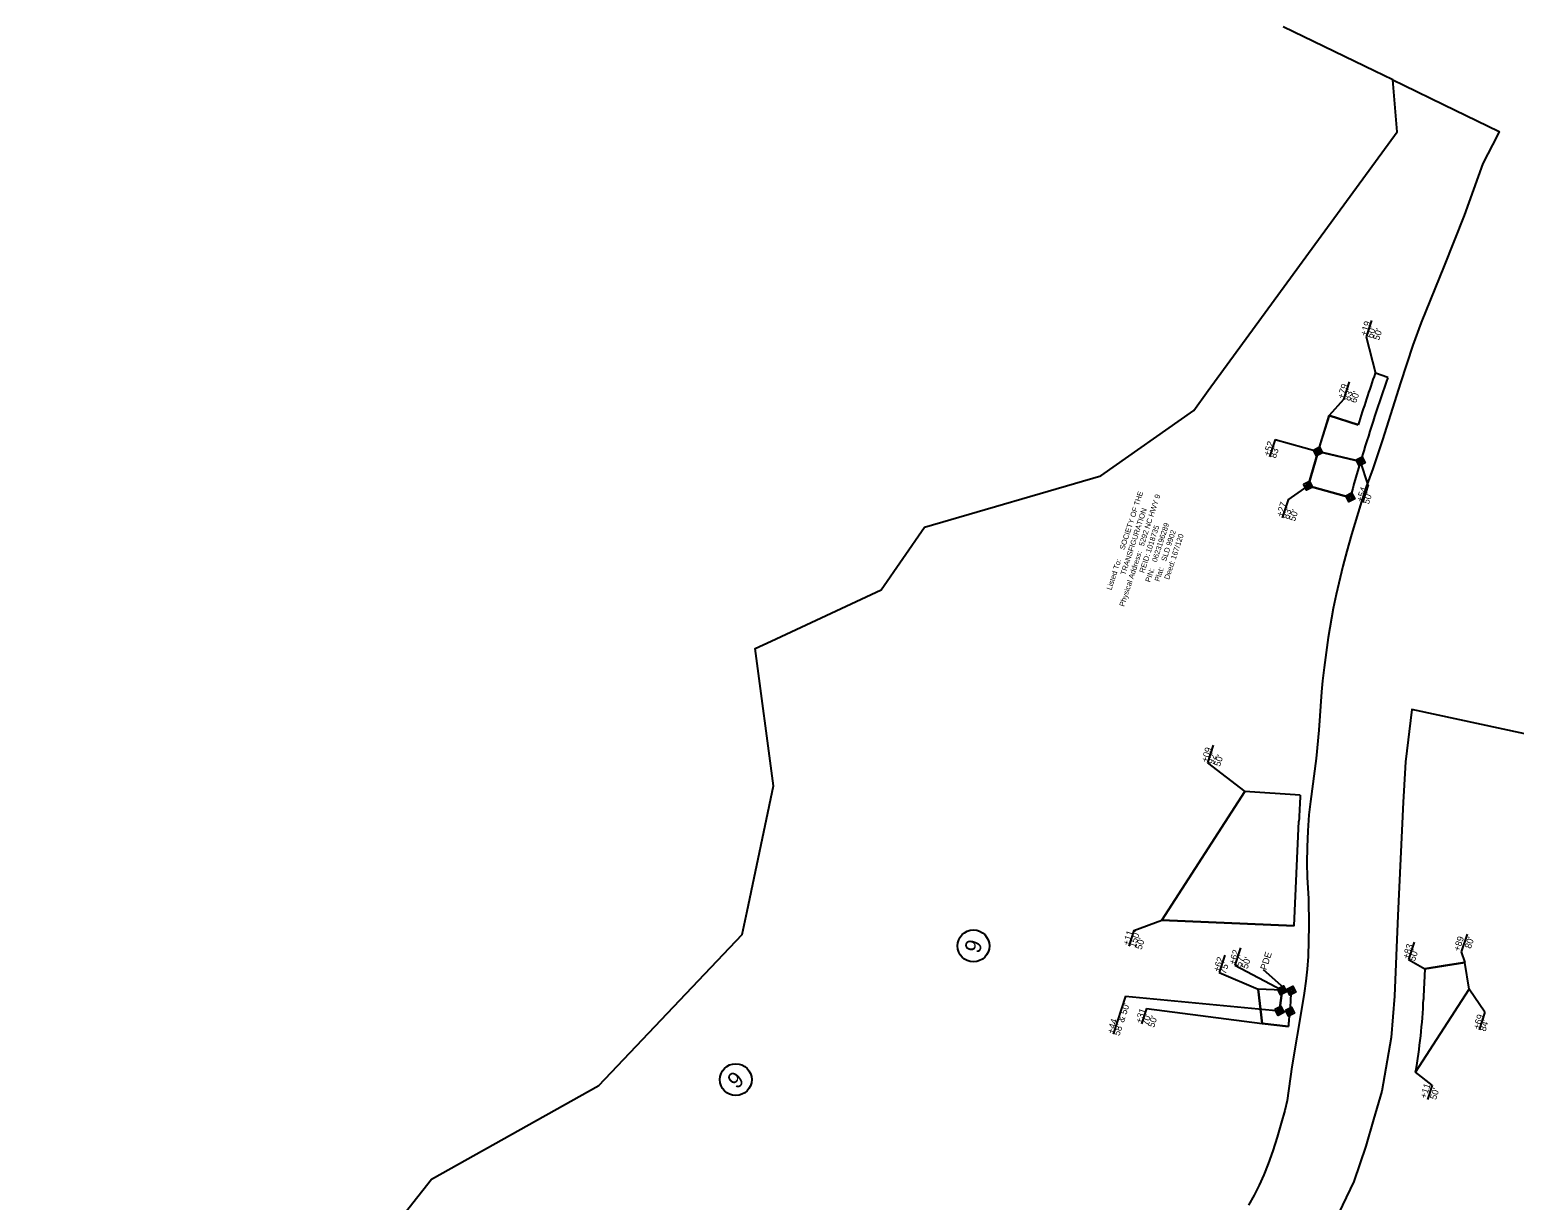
# Model space of a CAD drawing. Extents: x 1019969 to 1024963, y 638146 to 643978.
# Drawn here: x 1021048 to 1022170, y 639172 to 640057 of the extents above; entities that cross this region are included whole.
import ezdxf

# ---------------------------------------------------------------- set-up
doc = ezdxf.new("R2010")
doc.units = 0
for name, color, linetype in [('Old_Level_30', 7, 'Continuous'), ('Pattern 2', 7, 'Continuous'), ('Pattern 5', 7, 'Continuous'), ('Pattern 6', 7, 'Continuous'), ('Prop Easement Construction', 7, 'Continuous'), ('Prop Easement Construction Station Offsets', 7, 'Continuous'), ('Prop Easement Permanent Drainage', 7, 'Continuous'), ('Prop Easement Permanent Drainage Station Offsets', 7, 'Continuous'), ('Prop Parcel Number CELL', 7, 'Continuous'), ('Prop Parcel Owner Text', 7, 'Continuous'), ('Prop ROW Marker CELL', 7, 'Continuous'), ('Prop ROW Permanent Easement CELL', 7, 'Continuous'), ('Prop ROW RW Lines', 7, 'Continuous')]:
    doc.layers.add(name, color=color, linetype=linetype)

msp = doc.modelspace()

# ---------------------------------------------------------------- linework, layer by layer
at = {"layer": 'Old_Level_30'}
for points in [[(1021148.4, 638700.1), (1021154.9, 638708.9), (1021160.9, 638716.8), (1021048.3, 638820.3), (1021060.8, 638834.8), (1021201.8, 638998.1), (1021351.8, 639188.4), (1021478.2, 639259.2), (1021586.5, 639373.1), (1021590.2, 639390.9), (1021610.1, 639485.6), (1021596.2, 639589.1), (1021608.3, 639594.8), (1021691.4, 639633.5), (1021724, 639680.8), (1021857.3, 639719.7), (1021927.5, 639769), (1021938.4, 639784), (1022081, 639979.4), (1022077.7, 640018.6), (1022070.6, 640022.1), (1022064.2, 640025.1), (1021995.1, 640058.6)], [(1021201.8, 638998.1), (1021351.8, 639188.4), (1021478.2, 639259.2), (1021586.5, 639373.1), (1021590.2, 639390.9), (1021610.1, 639485.6), (1021596.2, 639589.1), (1021608.3, 639594.8), (1021691.4, 639633.5), (1021724, 639680.8), (1021857.3, 639719.7), (1021927.5, 639769), (1021938.4, 639784), (1022081, 639979.4), (1022077.7, 640018.6), (1022086, 640014.6), (1022116.1, 640000), (1022158.2, 639979.6), (1022156.8, 639977), (1022145.9, 639955.5), (1022131.6, 639916.3), (1022116.6, 639878.2), (1022099.2, 639835.5), (1022093, 639818.3), (1022083.7, 639789.8), (1022070.1, 639746.7), (1022062.7, 639724.9), (1022057.8, 639711.3), (1022054.1, 639700.1), (1022046.6, 639675.4), (1022043.1, 639662.6), (1022040.1, 639651.5), (1022035, 639630.1), (1022032.8, 639619.3), (1022028.9, 639597.4), (1022025.9, 639574.9), (1022024.8, 639564.9), (1022024, 639556.5), (1022022, 639527.6), (1022020, 639506.1), (1022015.6, 639473.7), (1022014.5, 639463.7), (1022013.6, 639451.6), (1022013.1, 639439.1), (1022012.9, 639427.2), (1022013.1, 639416.2), (1022014.1, 639400.5), (1022014.4, 639380), (1022013.8, 639356.5), (1022013, 639347.1), (1022012, 639337.9), (1022010.8, 639328.9), (1022009.4, 639319.7), (1022001.6, 639273.3), (1021998, 639247.9), (1021996.3, 639240.4), (1021993.6, 639230.6), (1021990.5, 639220.2), (1021987.1, 639209.8), (1021983.6, 639200.1), (1021980.4, 639191.8), (1021976.9, 639184), (1021973.2, 639176.4), (1021968.8, 639168.7)], [(1022449.9, 639466.2), (1022092.1, 639543.1), (1022087.5, 639503.7), (1022086, 639481.6), (1022085.7, 639473.2), (1022081.6, 639387.6), (1022079.1, 639326.7), (1022076.5, 639295.3), (1022069.4, 639254.8), (1022063.3, 639233.6), (1022057.4, 639213.4), (1022048.4, 639186.6), (1022033.9, 639156.6)]]:
    msp.add_lwpolyline(points, dxfattribs=at)
at = {"layer": 'Pattern 2'}
for p, q in [((1022021.3, 639738), (1022013.8, 639712.1)), ((1022053.5, 639730.5), (1022021.3, 639738)), ((1022013.8, 639712.1), (1022045.6, 639703.3)), ((1021994.2, 639331.1), (1021992.2, 639315.6)), ((1022001.2, 639330.8), (1021994.2, 639331.1)), ((1022001.1, 639328.7), (1022001.2, 639330.8)), ((1021992.2, 639315.6), (1022000.2, 639314.9))]:
    msp.add_line(p, q, dxfattribs=at)
for centre, radius, start, end in [((1023107.7, 639409.8), 1101.9, 163.0811, 164.5518), ((1021670.1, 639343.3), 331.3, 355.0689, 357.4575)]:
    msp.add_arc(centre, radius, start, end, dxfattribs=at)
at = {"layer": 'Pattern 6'}
for p, q in [((1022074, 639793.9), (1022064.6, 639797.2)), ((1022029.7, 639765.1), (1022023.3, 639744.5)), ((1022051.6, 639758.1), (1022029.7, 639765.1)), ((1022023.3, 639744.5), (1022021.3, 639738)), ((1022021.3, 639738), (1022053.5, 639730.5)), ((1022054.8, 639734.8), (1022054.8, 639734.8)), ((1021966, 639481.1), (1021903.4, 639384.1)), ((1022007.9, 639478.5), (1021966, 639481.1)), ((1022003.3, 639379.7), (1022006.9, 639458.7)), ((1021903.4, 639384.1), (1022003.3, 639379.7)), ((1022102, 639347.3), (1022101.1, 639326.3)), ((1022117.4, 639349.7), (1022102, 639347.3)), ((1022132.2, 639352), (1022117.4, 639349.7)), ((1022135.4, 639331.8), (1022132.2, 639352)), ((1021994.2, 639331.1), (1021976.2, 639331.9)), ((1021976.2, 639331.9), (1021979.2, 639306)), ((1021992.2, 639315.6), (1021994.2, 639331.1)), ((1022095, 639269.3), (1022135.4, 639331.8)), ((1022101.1, 639326.3), (1022101, 639324.2)), ((1022000.2, 639314.9), (1021992.2, 639315.6)), ((1021979.2, 639306), (1021999, 639303.6))]:
    msp.add_line(p, q, dxfattribs=at)
for centre, radius, start, end in [((1024054, 639117.2), 2102.5, 161.131, 162.2534), ((1024031.2, 639124.8), 2068.5, 161.1245, 162.8481), ((1023107.7, 639409.8), 1101.9, 162.8481, 163.0811), ((1023107.7, 639409.8), 1101.9, 176.4259, 177.4575), ((1021670.1, 639343.3), 431.3, 350.1105, 357.4575), ((1021387.6, 639372.6), 615.3, 353.5663, 354.6181)]:
    msp.add_arc(centre, radius, start, end, dxfattribs=at)
at = {"layer": 'Prop Easement Construction'}
for p, q in [((1022074, 639793.9), (1022064.6, 639797.2)), ((1022021.3, 639738), (1022029.7, 639765.1)), ((1022029.7, 639765.1), (1022051.6, 639758.1)), ((1021903.4, 639384.1), (1021966, 639481.1)), ((1022007.9, 639478.5), (1021966, 639481.1)), ((1022003.3, 639379.7), (1021903.4, 639384.1)), ((1022102, 639347.3), (1022132.2, 639352)), ((1022135.4, 639331.8), (1022132.2, 639352)), ((1021979.2, 639306), (1021976.2, 639331.9)), ((1021994.2, 639331.1), (1021976.2, 639331.9)), ((1022095, 639269.3), (1022135.4, 639331.8)), ((1021999, 639303.6), (1021979.2, 639306))]:
    msp.add_line(p, q, dxfattribs=at)
msp.add_arc((1024054, 639117.2), 2102.5, 161.131, 162.2534, dxfattribs=at)
at = {"layer": 'Prop Easement Construction Station Offsets'}
for p, q in [((1022061.8, 639836.9), (1022057.8, 639824.7)), ((1022044.8, 639790.7), (1022040.5, 639777.3)), ((1021942.1, 639516.2), (1021937.8, 639502.8)), ((1021882.2, 639376.1), (1021878.4, 639364.5)), ((1022133.9, 639373.5), (1022129.5, 639360)), ((1021951, 639357.6), (1021946.7, 639344.5)), ((1022094, 639367.5), (1022089.7, 639354.3)), ((1021891.7, 639317.4), (1021887.9, 639305.7)), ((1022147.4, 639314.5), (1022143, 639301.1)), ((1022107.6, 639259.4), (1022104.1, 639248.7))]:
    msp.add_line(p, q, dxfattribs=at)
for points in [[(1022057.8, 639824.7), (1022064.6, 639797.2)], [(1022040.5, 639777.3), (1022029.7, 639765.1)], [(1021937.8, 639502.8), (1021966, 639481.1)], [(1021882.2, 639376.1), (1021903.4, 639384.1)], [(1022129.5, 639360), (1022132.2, 639352)], [(1022089.7, 639354.3), (1022102, 639347.3)], [(1021946.7, 639344.5), (1021976.2, 639331.9)], [(1022147.4, 639314.5), (1022135.4, 639331.8)], [(1021891.7, 639317.4), (1021979.2, 639306)], [(1022107.6, 639259.4), (1022095, 639269.3)]]:
    msp.add_lwpolyline(points, dxfattribs=at)
at = {"layer": 'Prop Easement Permanent Drainage'}
for p, q in [((1022013.8, 639712.1), (1022021.3, 639738)), ((1022053.5, 639730.5), (1022021.3, 639738)), ((1022045.6, 639703.3), (1022013.8, 639712.1)), ((1021992.2, 639315.6), (1021994.2, 639331.1)), ((1022001.2, 639330.8), (1021994.2, 639331.1)), ((1022000.2, 639314.9), (1021992.2, 639315.6))]:
    msp.add_line(p, q, dxfattribs=at)
at = {"layer": 'Prop Easement Permanent Drainage Station Offsets'}
for p, q in [((1021988.9, 639747.1), (1021984.6, 639734)), ((1022059.3, 639712.8), (1022054.9, 639699.4)), ((1021998.7, 639701.6), (1021994.3, 639688)), ((1021962.7, 639363.1), (1021958.5, 639350)), ((1021875.9, 639326.5), (1021866.6, 639297.8))]:
    msp.add_line(p, q, dxfattribs=at)
for points in [[(1021988.9, 639747.1), (1022021.3, 639738)], [(1022059.3, 639712.8), (1022053.5, 639730.5)], [(1021998.7, 639701.6), (1022013.8, 639712.1)], [(1021958.5, 639350), (1021994.2, 639331.1)], [(1021979.9, 639346.7), (1021997.7, 639330.9)], [(1021875.9, 639326.5), (1021992.2, 639315.6)]]:
    msp.add_lwpolyline(points, dxfattribs=at)
at = {"layer": 'Prop Parcel Number CELL'}
for p, q in [((1021761.1, 639364.6), (1021761.1, 639364.6)), ((1021581.6, 639263.6), (1021581.6, 639263.6))]:
    msp.add_line(p, q, dxfattribs=at)
for centre in [(1021761.1, 639364.6), (1021581.6, 639263.6)]:
    msp.add_circle(centre, 12, dxfattribs=at)
at = {"layer": 'Prop ROW Marker CELL'}
for p, q in [((1022021.3, 639738), (1022021.3, 639738)), ((1022053.5, 639730.5), (1022053.5, 639730.5)), ((1022013.8, 639712.1), (1022013.8, 639712.1)), ((1022045.6, 639703.3), (1022045.6, 639703.3)), ((1021994.2, 639331.1), (1021994.2, 639331.1)), ((1022001.2, 639330.8), (1022001.2, 639330.8)), ((1021992.2, 639315.6), (1021992.2, 639315.6)), ((1022000.2, 639314.9), (1022000.2, 639314.9))]:
    msp.add_line(p, q, dxfattribs=at)
at = {"layer": 'Prop ROW Permanent Easement CELL'}
for points in [[(1022017.8, 639739.1), (1022022.4, 639741.4), (1022024.7, 639736.9), (1022020.2, 639734.6)], [(1022019.6, 639738.6), (1022021.8, 639739.7), (1022023, 639737.5), (1022020.7, 639736.3)], [(1022050, 639731.6), (1022054.6, 639733.9), (1022056.9, 639729.4), (1022052.3, 639727.1)], [(1022051.8, 639731), (1022054, 639732.2), (1022055.2, 639729.9), (1022052.9, 639728.8)], [(1022010.3, 639713.2), (1022014.9, 639715.5), (1022017.2, 639711), (1022012.7, 639708.7)], [(1022012.1, 639712.7), (1022014.3, 639713.8), (1022015.5, 639711.6), (1022013.2, 639710.4)], [(1022042.2, 639704.4), (1022046.7, 639706.7), (1022049, 639702.2), (1022044.5, 639699.9)], [(1022043.9, 639703.9), (1022046.1, 639705), (1022047.3, 639702.8), (1022045, 639701.6)], [(1021990.8, 639332.2), (1021995.3, 639334.5), (1021997.6, 639330), (1021993.1, 639327.6)], [(1021992.5, 639331.6), (1021994.7, 639332.8), (1021995.9, 639330.5), (1021993.6, 639329.4)], [(1021997.7, 639331.9), (1022002.3, 639334.2), (1022004.6, 639329.6), (1022000.1, 639327.3)], [(1021999.5, 639331.3), (1022001.7, 639332.5), (1022002.9, 639330.2), (1022000.6, 639329)], [(1021988.8, 639316.7), (1021993.3, 639319), (1021995.6, 639314.4), (1021991.1, 639312.1)], [(1021990.5, 639316.1), (1021992.8, 639317.3), (1021993.9, 639315), (1021991.7, 639313.8)], [(1021996.8, 639316), (1022001.3, 639318.3), (1022003.6, 639313.8), (1021999.1, 639311.4)], [(1021998.5, 639315.4), (1022000.7, 639316.6), (1022001.9, 639314.3), (1021999.6, 639313.2)]]:
    msp.add_lwpolyline(points, close=True, dxfattribs=at)
at = {"layer": 'Prop ROW RW Lines'}
msp.add_arc((1022167.9, 640774.2), 948.1, 40.0024, 40.0024, dxfattribs=at)

# ---------------------------------------------------------------- texts
at = {"layer": 'Pattern 5'}
for s, p in [('SOCIETY OF THE ', (1021875.1, 639663.4)), ('TRANSFIGURATION', (1021875.8, 639644.3)), ('5292 NC HWY 9', (1021889.7, 639666.1)), ('0623196289', (1021899.5, 639654.1)), ('1018735', (1021894.9, 639661.1)), ('SLD 9902', (1021906.5, 639654.6)), ('167/120', (1021913.8, 639656.1)), ('Physical Address:', (1021874.9, 639620.5)), ('Listed To:', (1021865.3, 639633)), ('REID:', (1021890, 639645.9)), ('PIN:', (1021894.5, 639638.9)), ('Plat:', (1021901.5, 639639.4)), ('Deed:', (1021908.8, 639640.9))]:
    msp.add_text(s, height=4, rotation=71.9892, dxfattribs=at).set_placement(p)
at = {"layer": 'Prop Easement Construction Station Offsets'}
for s, rotation, p in [('+19', 71.9903, (1022057.8, 639824.7)), ("60'", 71.9903, (1022062.6, 639823.1)), ("50'", 71.9903, (1022067.4, 639821.6)), ('+79', 71.9903, (1022040.5, 639777.3)), ("83'", 71.9903, (1022045.3, 639775.8)), ("60'", 71.9903, (1022050.1, 639774.2)), ('+09', 71.9903, (1021937.7, 639502.8)), ("92'", 71.9903, (1021942.5, 639501.3)), ("50'", 71.9903, (1021947.3, 639499.7)), ('+11', 71.9903, (1021878.4, 639364.5)), ("150'", 71.9903, (1021883.2, 639362.9)), ("50'", 71.9903, (1021888, 639361.4)), ('+89', 71.9915, (1022128.2, 639360.1)), ("80'", 71.9915, (1022136.7, 639362.1)), ('+83', 71.9903, (1022089.7, 639354.3)), ("50'", 71.9903, (1022094.5, 639352.7)), ('+62', 71.9903, (1021946.7, 639344.5)), ("75'", 71.9903, (1021951.5, 639343)), ('+31', 71.9903, (1021887.9, 639305.7)), ("70'", 71.9903, (1021892.7, 639304.1)), ('+69', 71.9903, (1022143, 639301.1)), ("50'", 71.9903, (1021897.5, 639302.6)), ("84'", 71.9903, (1022147.8, 639299.6)), ('+11', 71.9903, (1022102.9, 639249)), ("50'", 71.9903, (1022110.4, 639248))]:
    msp.add_text(s, height=5, rotation=rotation, dxfattribs=at).set_placement(p)
at = {"layer": 'Prop Easement Permanent Drainage Station Offsets'}
for s, p in [('+52', (1021984.6, 639734)), ("83'", (1021989.4, 639732.5)), ('+54', (1022054.9, 639699.4)), ("50'", (1022059.7, 639697.8)), ('+27', (1021994.3, 639688.1)), ("83'", (1021999.1, 639686.5)), ("50'", (1022003.9, 639684.9)), ('+62', (1021958.5, 639350)), ("57'", (1021963.3, 639348.4)), ('PDE', (1021982.3, 639346)), ("50'", (1021968.1, 639346.9)), ("58' & 50'", (1021871.3, 639296.3)), ('+44', (1021866.5, 639297.8))]:
    msp.add_text(s, height=5, rotation=71.9903, dxfattribs=at).set_placement(p)
at = {"layer": 'Prop Parcel Owner Text'}
for rotation, p in [(71.9892, (1021765.4, 639358.2)), (44.2601, (1021582.4, 639255.9))]:
    msp.add_text('9', height=12.2, rotation=rotation, dxfattribs=at).set_placement(p)

doc.saveas('drawing.dxf')
